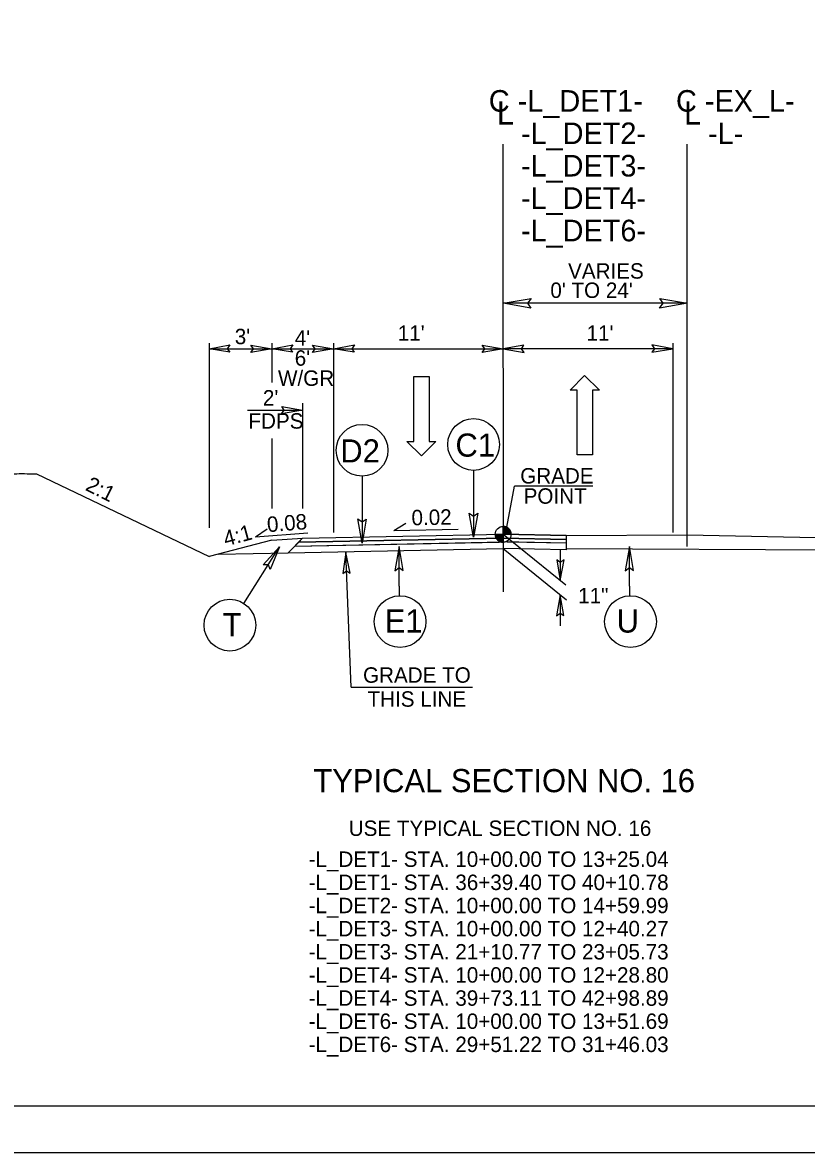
# Model space of a CAD drawing. Extents: x 18938 to 19565, y 6931 to 7973.
# Drawn here: x 19298.4 to 19349.2, y 7077.8 to 7151 of the extents above; entities that cross this region are included whole.
import ezdxf

# ---------------------------------------------------------------- set-up
doc = ezdxf.new("R2010")
doc.units = 0
for name, color, linetype in [('Old_Level_11', 7, 'Continuous'), ('Old_Level_3', 7, 'Continuous'), ('Prop Dimension', 7, 'Continuous'), ('Prop Pavement Schedule Description CELL', 7, 'Continuous'), ('Prop Shade Medium', 7, 'Continuous'), ('Prop Terminator CELL', 7, 'Continuous'), ('Sheet Block Title CELL', 7, 'Continuous'), ('Sheet Data Field CELL', 7, 'Continuous'), ('Sheet Plot Border Outside CELL', 7, 'Continuous'), ('Sheet Typical CELL', 7, 'Continuous'), ('Typical Curb CELL', 7, 'Continuous'), ('Typical Detail Wedge1 CELL', 7, 'Continuous'), ('Typical Detail Wedge2 CELL', 7, 'Continuous'), ('Typical Detail Wedge3 CELL', 7, 'Continuous'), ('Typical Hinge Slope Arterial CELL', 7, 'Continuous'), ('Typical Pavement Slope Information CELL', 7, 'Continuous'), ('Typical Shoulder Slope Information CELL', 7, 'Continuous'), ('Typical Terminator CELL', 7, 'Continuous'), ('Typical Text General CELL', 7, 'Continuous'), ('Typical Text Grade Point CELL', 7, 'Continuous'), ('Typical Text ID Circle CELL', 7, 'Continuous'), ('Typical Text Label CELL', 7, 'Continuous')]:
    doc.layers.add(name, color=color, linetype=linetype)

msp = doc.modelspace()

# ---------------------------------------------------------------- linework, layer by layer
at = {"layer": 'Old_Level_3'}
for p, q in [((19341.525, 7132.796), (19329.572, 7132.796)), ((19333.666, 7117.747), (19341.511, 7117.793)), ((19341.511, 7117.793), (19354.599, 7117.507)), ((19353.866, 7116.774), (19333.666, 7116.889))]:
    msp.add_line(p, q, dxfattribs=at)
at = {"layer": 'Prop Dimension'}
msp.add_lwpolyline([(19155.167, 7077.771), (19382.434, 7077.771), (19382.434, 7224.204), (19155.167, 7224.204)], close=True, dxfattribs=at)
at = {"layer": 'Prop Pavement Schedule Description CELL'}
for p, q in [((19314.572, 7117.446), (19316.572, 7117.569)), ((19315.637, 7116.634), (19316.572, 7117.569)), ((19316.317, 7117.314), (19329.572, 7117.579)), ((19316.572, 7117.569), (19329.572, 7117.829)), ((19333.666, 7117.747), (19329.572, 7117.829)), ((19333.666, 7117.497), (19329.572, 7117.579)), ((19333.666, 7117.747), (19333.666, 7116.831)), ((19315.637, 7116.634), (19329.585, 7116.913)), ((19316.062, 7117.059), (19329.317, 7117.324)), ((19333.666, 7116.831), (19329.558, 7116.913)), ((19333.666, 7117.247), (19329.827, 7117.324)), ((19311.097, 7116.543), (19315.637, 7116.634))]:
    msp.add_line(p, q, dxfattribs=at)
at = {"layer": 'Prop Shade Medium'}
for p in [(19299.33, 7121.735), (19314.572, 7117.446)]:
    msp.add_line(p, (19310.505, 7116.389), dxfattribs=at)
at = {"layer": 'Sheet Block Title CELL'}
for p, q in [((19329.572, 7117.579), (19316.317, 7117.314)), ((19329.572, 7117.579), (19316.317, 7117.314)), ((19329.572, 7117.329), (19329.572, 7117.579)), ((19329.572, 7117.579), (19333.666, 7117.497)), ((19329.572, 7117.329), (19329.572, 7117.579)), ((19329.572, 7117.329), (19329.572, 7117.579)), ((19333.666, 7117.497), (19333.666, 7117.247)), ((19316.062, 7117.059), (19329.572, 7117.329)), ((19316.062, 7117.059), (19329.572, 7117.329)), ((19316.317, 7117.314), (19316.062, 7117.059)), ((19316.317, 7117.314), (19316.062, 7117.059)), ((19333.666, 7117.247), (19329.572, 7117.329))]:
    msp.add_line(p, q, dxfattribs=at)
at = {"layer": 'Sheet Data Field CELL'}
for points in [[(19331.372, 7132.486), (19329.572, 7132.796), (19331.382, 7133.116), (19331.152, 7132.796)], [(19339.725, 7133.106), (19341.525, 7132.796), (19339.715, 7132.476), (19339.945, 7132.796)], [(19311.855, 7129.623), (19310.505, 7129.855), (19311.862, 7130.095), (19311.69, 7129.855)], [(19313.222, 7130.088), (19314.572, 7129.855), (19313.214, 7129.615), (19313.387, 7129.855)], [(19315.922, 7129.623), (19314.572, 7129.855), (19315.929, 7130.095), (19315.757, 7129.855)], [(19317.222, 7130.088), (19318.572, 7129.855), (19317.214, 7129.615), (19317.387, 7129.855)], [(19319.922, 7129.623), (19318.572, 7129.855), (19319.929, 7130.095), (19319.757, 7129.855)], [(19328.222, 7130.088), (19329.572, 7129.855), (19328.214, 7129.615), (19328.387, 7129.855)], [(19330.922, 7130.088), (19329.572, 7129.855), (19330.929, 7129.615), (19330.757, 7129.855)], [(19339.222, 7129.623), (19340.572, 7129.855), (19339.214, 7130.095), (19339.387, 7129.855)], [(19315.222, 7126.109), (19316.572, 7125.876), (19315.214, 7125.636), (19315.387, 7125.876)], [(19319.647, 7115.304), (19319.369, 7116.645), (19319.175, 7115.28), (19319.409, 7115.461)], [(19333.049, 7116.174), (19333.281, 7114.824), (19333.521, 7116.182), (19333.281, 7116.009)], [(19333.513, 7112.558), (19333.281, 7113.908), (19333.041, 7112.551), (19333.281, 7112.723)]]:
    msp.add_lwpolyline(points, close=True, dxfattribs=at)
at = {"layer": 'Sheet Typical CELL'}
for p, q in [((19310.505, 7130.208), (19310.505, 7118.256)), ((19310.505, 7129.855), (19314.572, 7129.855)), ((19314.572, 7130.208), (19314.572, 7127.672)), ((19314.572, 7129.855), (19318.572, 7129.855)), ((19318.572, 7130.208), (19318.572, 7117.941)), ((19318.572, 7129.855), (19329.572, 7129.855)), ((19340.572, 7129.855), (19329.572, 7129.855)), ((19340.572, 7130.208), (19340.572, 7117.941)), ((19316.572, 7126.335), (19316.572, 7119.499)), ((19313.001, 7125.876), (19316.572, 7125.876)), ((19314.572, 7124.038), (19314.572, 7119.499)), ((19329.572, 7117.829), (19333.627, 7114.544)), ((19329.572, 7116.912), (19333.677, 7113.587)), ((19333.281, 7116.868), (19333.281, 7114.824)), ((19319.71, 7107.916), (19319.369, 7116.645)), ((19322.824, 7114.464), (19322.824, 7113.844)), ((19333.281, 7113.908), (19333.281, 7111.885)), ((19337.763, 7114.464), (19337.763, 7113.844)), ((19319.71, 7107.916), (19327.579, 7107.916))]:
    msp.add_line(p, q, dxfattribs=at)
at = {"layer": 'Typical Curb CELL'}
msp.add_spline([(19288.966, 7121.735), (19289.137, 7121.735), (19289.137, 7121.649), (19289.308, 7121.649), (19289.394, 7121.564), (19290.079, 7121.564), (19290.165, 7121.649), (19291.364, 7121.735), (19292.306, 7121.735), (19292.392, 7121.649), (19292.649, 7121.649), (19294.105, 7121.821), (19294.705, 7121.821), (19294.705, 7121.735), (19295.304, 7121.735), (19295.39, 7121.649), (19295.475, 7121.649), (19295.904, 7121.649), (19295.989, 7121.564), (19296.589, 7121.564), (19296.589, 7121.649), (19296.674, 7121.649), (19297.874, 7121.735), (19299.244, 7121.735), (19299.33, 7121.735)], degree=3, dxfattribs=at)
at = {"layer": 'Typical Detail Wedge1 CELL'}
for p, q in [((19329.572, 7117.829), (19329.572, 7118.341)), ((19329.06, 7117.829), (19329.572, 7117.829)), ((19330.084, 7117.829), (19329.572, 7117.829)), ((19329.572, 7117.317), (19329.572, 7117.829)), ((19329.572, 7117.829), (19329.572, 7117.317))]:
    msp.add_line(p, q, dxfattribs=at)
for points in [[(19329.577, 7118.341), (19329.577, 7118.341), (19329.577, 7117.829)], [(19329.587, 7118.34), (19329.587, 7117.829)], [(19329.597, 7118.34), (19329.597, 7117.829)], [(19329.608, 7118.339), (19329.607, 7117.829)], [(19329.618, 7118.338), (19329.618, 7117.829)], [(19329.628, 7118.338), (19329.628, 7117.829)], [(19329.638, 7118.336), (19329.638, 7117.829)], [(19329.649, 7118.335), (19329.649, 7117.829)], [(19329.659, 7118.333), (19329.659, 7117.829)], [(19329.669, 7118.331), (19329.669, 7117.829)], [(19329.679, 7118.329), (19329.679, 7117.829)], [(19329.69, 7118.327), (19329.69, 7117.829)], [(19329.7, 7118.325), (19329.7, 7117.829)], [(19329.71, 7118.322), (19329.71, 7117.829)], [(19329.72, 7118.319), (19329.72, 7117.829)], [(19329.731, 7118.316), (19329.731, 7117.829)], [(19329.741, 7118.312), (19329.741, 7117.829)], [(19329.751, 7118.308), (19329.751, 7117.829)], [(19329.761, 7118.304), (19329.761, 7117.829)], [(19329.772, 7118.3), (19329.771, 7117.829)], [(19329.782, 7118.295), (19329.782, 7117.829)], [(19329.792, 7118.291), (19329.792, 7117.829)], [(19329.802, 7118.286), (19329.802, 7117.829)], [(19329.812, 7118.28), (19329.812, 7117.829)], [(19329.823, 7118.275), (19329.822, 7117.829)], [(19329.833, 7118.269), (19329.833, 7117.829)], [(19329.843, 7118.263), (19329.843, 7117.829)], [(19329.853, 7118.256), (19329.853, 7117.829)], [(19329.864, 7118.249), (19329.864, 7117.829)], [(19329.874, 7118.242), (19329.874, 7117.829)], [(19329.884, 7118.234), (19329.884, 7117.829)], [(19329.895, 7118.226), (19329.894, 7117.829)], [(19329.905, 7118.218), (19329.905, 7117.829)], [(19329.915, 7118.208), (19329.915, 7117.828)], [(19329.925, 7118.199), (19329.925, 7117.829)], [(19329.935, 7118.189), (19329.935, 7117.828)], [(19329.946, 7118.179), (19329.946, 7117.828)], [(19329.956, 7118.167), (19329.956, 7117.829)], [(19329.966, 7118.155), (19329.966, 7117.828)], [(19329.976, 7118.142), (19329.976, 7117.828)], [(19329.063, 7117.829), (19329.063, 7117.773)], [(19329.073, 7117.829), (19329.073, 7117.713)], [(19329.083, 7117.829), (19329.083, 7117.675)], [(19329.094, 7117.829), (19329.094, 7117.646)], [(19329.104, 7117.829), (19329.104, 7117.621)], [(19329.114, 7117.829), (19329.114, 7117.599)], [(19329.124, 7117.829), (19329.124, 7117.58)], [(19329.134, 7117.829), (19329.134, 7117.563)], [(19329.145, 7117.829), (19329.145, 7117.547)], [(19329.155, 7117.829), (19329.155, 7117.531)], [(19329.165, 7117.829), (19329.165, 7117.518)], [(19329.175, 7117.829), (19329.175, 7117.505)], [(19329.186, 7117.829), (19329.186, 7117.492)], [(19329.196, 7117.829), (19329.196, 7117.481)], [(19329.206, 7117.829), (19329.206, 7117.47)], [(19329.217, 7117.829), (19329.216, 7117.46)], [(19329.227, 7117.829), (19329.227, 7117.451)], [(19329.237, 7117.829), (19329.237, 7117.442)], [(19329.247, 7117.829), (19329.247, 7117.433)], [(19329.257, 7117.829), (19329.257, 7117.424)], [(19329.268, 7117.829), (19329.268, 7117.417)], [(19329.278, 7117.829), (19329.278, 7117.409)], [(19329.288, 7117.829), (19329.288, 7117.402)], [(19329.298, 7117.829), (19329.298, 7117.396)], [(19329.309, 7117.829), (19329.308, 7117.389)], [(19329.319, 7117.829), (19329.319, 7117.383)], [(19329.329, 7117.829), (19329.329, 7117.378)], [(19329.339, 7117.829), (19329.339, 7117.373)], [(19329.349, 7117.829), (19329.349, 7117.367)], [(19329.36, 7117.829), (19329.36, 7117.363)], [(19329.37, 7117.829), (19329.37, 7117.358)], [(19329.38, 7117.829), (19329.38, 7117.354)], [(19329.391, 7117.829), (19329.391, 7117.35)], [(19329.401, 7117.829), (19329.401, 7117.346)], [(19329.411, 7117.829), (19329.411, 7117.342)], [(19329.421, 7117.829), (19329.421, 7117.339)], [(19329.432, 7117.829), (19329.431, 7117.336)], [(19329.442, 7117.829), (19329.442, 7117.333)], [(19329.452, 7117.829), (19329.452, 7117.331)], [(19329.462, 7117.829), (19329.462, 7117.328)], [(19329.473, 7117.829), (19329.472, 7117.326)], [(19329.483, 7117.829), (19329.483, 7117.325)], [(19329.493, 7117.829), (19329.493, 7117.323)], [(19329.503, 7117.829), (19329.503, 7117.321)], [(19329.513, 7117.829), (19329.513, 7117.32)], [(19329.524, 7117.829), (19329.523, 7117.319)], [(19329.534, 7117.829), (19329.534, 7117.318)], [(19329.544, 7117.829), (19329.544, 7117.318)], [(19329.554, 7117.829), (19329.554, 7117.317)], [(19329.565, 7117.829), (19329.565, 7117.317), (19329.565, 7117.317)], [(19329.987, 7118.129), (19329.986, 7117.829)], [(19329.997, 7118.114), (19329.997, 7117.828)], [(19330.007, 7118.098), (19330.007, 7117.828)], [(19330.017, 7118.081), (19330.017, 7117.829)], [(19330.027, 7118.062), (19330.027, 7117.828)], [(19330.038, 7118.041), (19330.038, 7117.828)], [(19330.048, 7118.017), (19330.048, 7117.829)], [(19330.058, 7117.989), (19330.058, 7117.828)], [(19330.069, 7117.953), (19330.069, 7117.828)], [(19330.079, 7117.901), (19330.079, 7117.829)]]:
    msp.add_lwpolyline(points, dxfattribs=at)
msp.add_circle((19329.572, 7117.829), 0.512, dxfattribs=at)
for start, end in [(359.99048, 89.99048), (179.99048, 269.99048)]:
    msp.add_arc((19329.572, 7117.829), 0.512, start, end, dxfattribs=at)
at = {"layer": 'Typical Detail Wedge3 CELL'}
for p, q in [((19323.779, 7123.847), (19323.779, 7128.047)), ((19323.779, 7128.047), (19324.769, 7128.047)), ((19324.769, 7128.047), (19324.769, 7123.847)), ((19333.925, 7127.176), (19334.855, 7128.121)), ((19334.855, 7128.121), (19335.815, 7127.176)), ((19334.375, 7127.176), (19333.925, 7127.176)), ((19334.375, 7122.976), (19334.375, 7127.176)), ((19335.815, 7127.176), (19335.365, 7127.176)), ((19335.365, 7127.176), (19335.365, 7122.976)), ((19324.289, 7122.902), (19323.329, 7123.847)), ((19323.329, 7123.847), (19323.779, 7123.847)), ((19325.219, 7123.847), (19324.289, 7122.902)), ((19324.769, 7123.847), (19325.219, 7123.847)), ((19335.365, 7122.976), (19334.375, 7122.976))]:
    msp.add_line(p, q, dxfattribs=at)
at = {"layer": 'Typical Hinge Slope Arterial CELL'}
for p, q in [((19316.317, 7117.314), (19316.572, 7117.569)), ((19316.572, 7117.569), (19329.572, 7117.829)), ((19329.572, 7117.579), (19316.572, 7117.319)), ((19329.572, 7117.829), (19333.666, 7117.747)), ((19333.666, 7117.497), (19329.572, 7117.579)), ((19333.666, 7117.747), (19333.666, 7117.497)), ((19316.572, 7117.319), (19316.317, 7117.314)), ((19316.572, 7117.319), (19316.572, 7117.319))]:
    msp.add_line(p, q, dxfattribs=at)
at = {"layer": 'Typical Pavement Slope Information CELL'}
msp.add_lwpolyline([(19380.142, 7221.197), (19177.642, 7221.197), (19177.642, 7080.781), (19380.142, 7080.781)], close=True, dxfattribs=at)
at = {"layer": 'Typical Terminator CELL'}
for p, q in [((19327.656, 7121.972), (19327.656, 7117.64)), ((19320.426, 7121.594), (19320.426, 7117.263)), ((19312.756, 7113.353), (19315.083, 7117.006)), ((19322.824, 7114.464), (19322.824, 7117.027)), ((19337.763, 7114.464), (19337.763, 7117.027))]:
    msp.add_line(p, q, dxfattribs=at)
for centre in [(19320.426, 7123.27), (19327.656, 7123.647), (19322.891, 7112.169), (19337.83, 7112.169), (19311.856, 7111.94)]:
    msp.add_circle(centre, 1.676, dxfattribs=at)
at = {"layer": 'Typical Text General CELL'}
for points in [[(19327.924, 7119.192), (19327.656, 7117.64), (19327.38, 7119.201), (19327.656, 7119.003)], [(19320.693, 7118.815), (19320.426, 7117.263), (19320.15, 7118.823), (19320.426, 7118.625)], [(19314.024, 7115.841), (19315.083, 7117.006), (19314.477, 7115.542), (19314.351, 7115.857)], [(19323.091, 7115.476), (19322.824, 7117.027), (19322.548, 7115.467), (19322.824, 7115.665)], [(19338.03, 7115.476), (19337.763, 7117.027), (19337.487, 7115.467), (19337.763, 7115.665)]]:
    msp.add_lwpolyline(points, close=True, dxfattribs=at)
at = {"layer": 'Typical Text Grade Point CELL'}
for p, q in [((19313.522, 7117.657), (19314.275, 7118.176)), ((19322.476, 7118.069), (19323.259, 7118.542)), ((19322.476, 7118.069), (19326.665, 7118.153)), ((19313.522, 7117.657), (19316.908, 7117.928))]:
    msp.add_line(p, q, dxfattribs=at)
at = {"layer": 'Typical Text ID Circle CELL'}
for p, q in [((19329.557, 7143.113), (19329.572, 7114.092)), ((19341.511, 7117.041), (19341.51, 7143.113)), ((19329.822, 7118.282), (19330.317, 7120.95)), ((19335.394, 7120.949), (19330.317, 7120.95))]:
    msp.add_line(p, q, dxfattribs=at)

# ---------------------------------------------------------------- texts
at = {"layer": 'Old_Level_11'}
for s, height, p in [('TYPICAL SECTION NO. 16', 1.5, (19317.267, 7101.113)), ('USE TYPICAL SECTION NO. 16', 1, (19319.562, 7098.279))]:
    msp.add_text(s, height=height, dxfattribs=at).set_placement(p)
at = {"layer": 'Old_Level_3'}
for s, p in [('VARIES ', (19333.784, 7134.394)), ("0' TO 24'", (19332.634, 7133.144))]:
    msp.add_text(s, height=1, dxfattribs=at).set_placement(p)
at = {"layer": 'Prop Terminator CELL'}
for s, p in [('D2', (19319.016, 7122.481)), ('C1', (19326.483, 7122.859))]:
    msp.add_text(s, height=1.5, dxfattribs=at).set_placement(p)
for s, p in [('T', (19311.387, 7111.22)), ('E1', (19321.899, 7111.458)), ('U', (19336.927, 7111.458))]:
    msp.add_text(s, height=1.5, rotation=360, dxfattribs=at).set_placement(p)
at = {"layer": 'Sheet Plot Border Outside CELL'}
for s, p in [('GRADE', (19330.683, 7121.118)), ('POINT', (19330.901, 7119.807))]:
    msp.add_text(s, height=1, rotation=0.00004, dxfattribs=at).set_placement(p)
at = {"layer": 'Typical Detail Wedge2 CELL'}
for s, p in [("11'", (19322.742, 7130.365)), ("11'", (19334.981, 7130.365)), ("3'", (19312.175, 7130.145)), ("4'", (19316.062, 7130.055)), ("6' ", (19316.062, 7128.751)), ('W/GR', (19314.977, 7127.446)), ("2'", (19314, 7126.173)), ('FDPS', (19313.06, 7124.673)), ('11"', (19334.438, 7113.354)), ('GRADE TO', (19320.491, 7108.207)), ('THIS LINE', (19320.782, 7106.652)), ('-L_DET1- STA. 10+00.00 TO 13+25.04', (19316.961, 7096.273)), ('-L_DET1- STA. 36+39.40 TO 40+10.78', (19316.961, 7094.773)), ('-L_DET2- STA. 10+00.00 TO 14+59.99', (19316.961, 7093.273)), ('-L_DET3- STA. 10+00.00 TO 12+40.27', (19316.961, 7091.773)), ('-L_DET3- STA. 21+10.77 TO 23+05.73', (19316.961, 7090.273)), ('-L_DET4- STA. 10+00.00 TO 12+28.80', (19316.961, 7088.773)), ('-L_DET4- STA. 39+73.11 TO 42+98.89', (19316.961, 7087.273)), ('-L_DET6- STA. 10+00.00 TO 13+51.69', (19316.961, 7085.773)), ('-L_DET6- STA. 29+51.22 TO 31+46.03', (19316.961, 7084.273))]:
    msp.add_text(s, height=1, dxfattribs=at).set_placement(p)
at = {"layer": 'Typical Shoulder Slope Information CELL'}
for s, rotation, p in [('2:1', 333.43491, (19302.427, 7120.718)), ('4:1', 15.1346, (19311.59, 7117.033))]:
    msp.add_text(s, height=1, rotation=rotation, dxfattribs=at).set_placement(p)
at = {"layer": 'Typical Text Grade Point CELL'}
for s, rotation, p in [('0.08', 4.5738, (19314.303, 7117.958)), ('0.02', 1.14574, (19323.643, 7118.404))]:
    msp.add_text(s, height=1, rotation=rotation, dxfattribs=at).set_placement(p)
at = {"layer": 'Typical Text Label CELL'}
for s, height, p in [('C -L_DET1- ', 1.4, (19328.643, 7145.213)), ('C -EX_L- ', 1.4, (19340.779, 7145.213)), ('L', 1.5, (19329.161, 7144.377)), ('L', 1.5, (19341.297, 7144.376)), ('    -L_DET2-   ', 1.4, (19328.643, 7143.113)), ('    -L-   ', 1.4, (19340.779, 7143.113)), ('    -L_DET3-   ', 1.4, (19328.643, 7141.013)), ('    -L_DET4-', 1.4, (19328.643, 7138.913)), ('    -L_DET6-', 1.4, (19328.643, 7136.813))]:
    msp.add_text(s, height=height, dxfattribs=at).set_placement(p)

doc.saveas('drawing.dxf')
